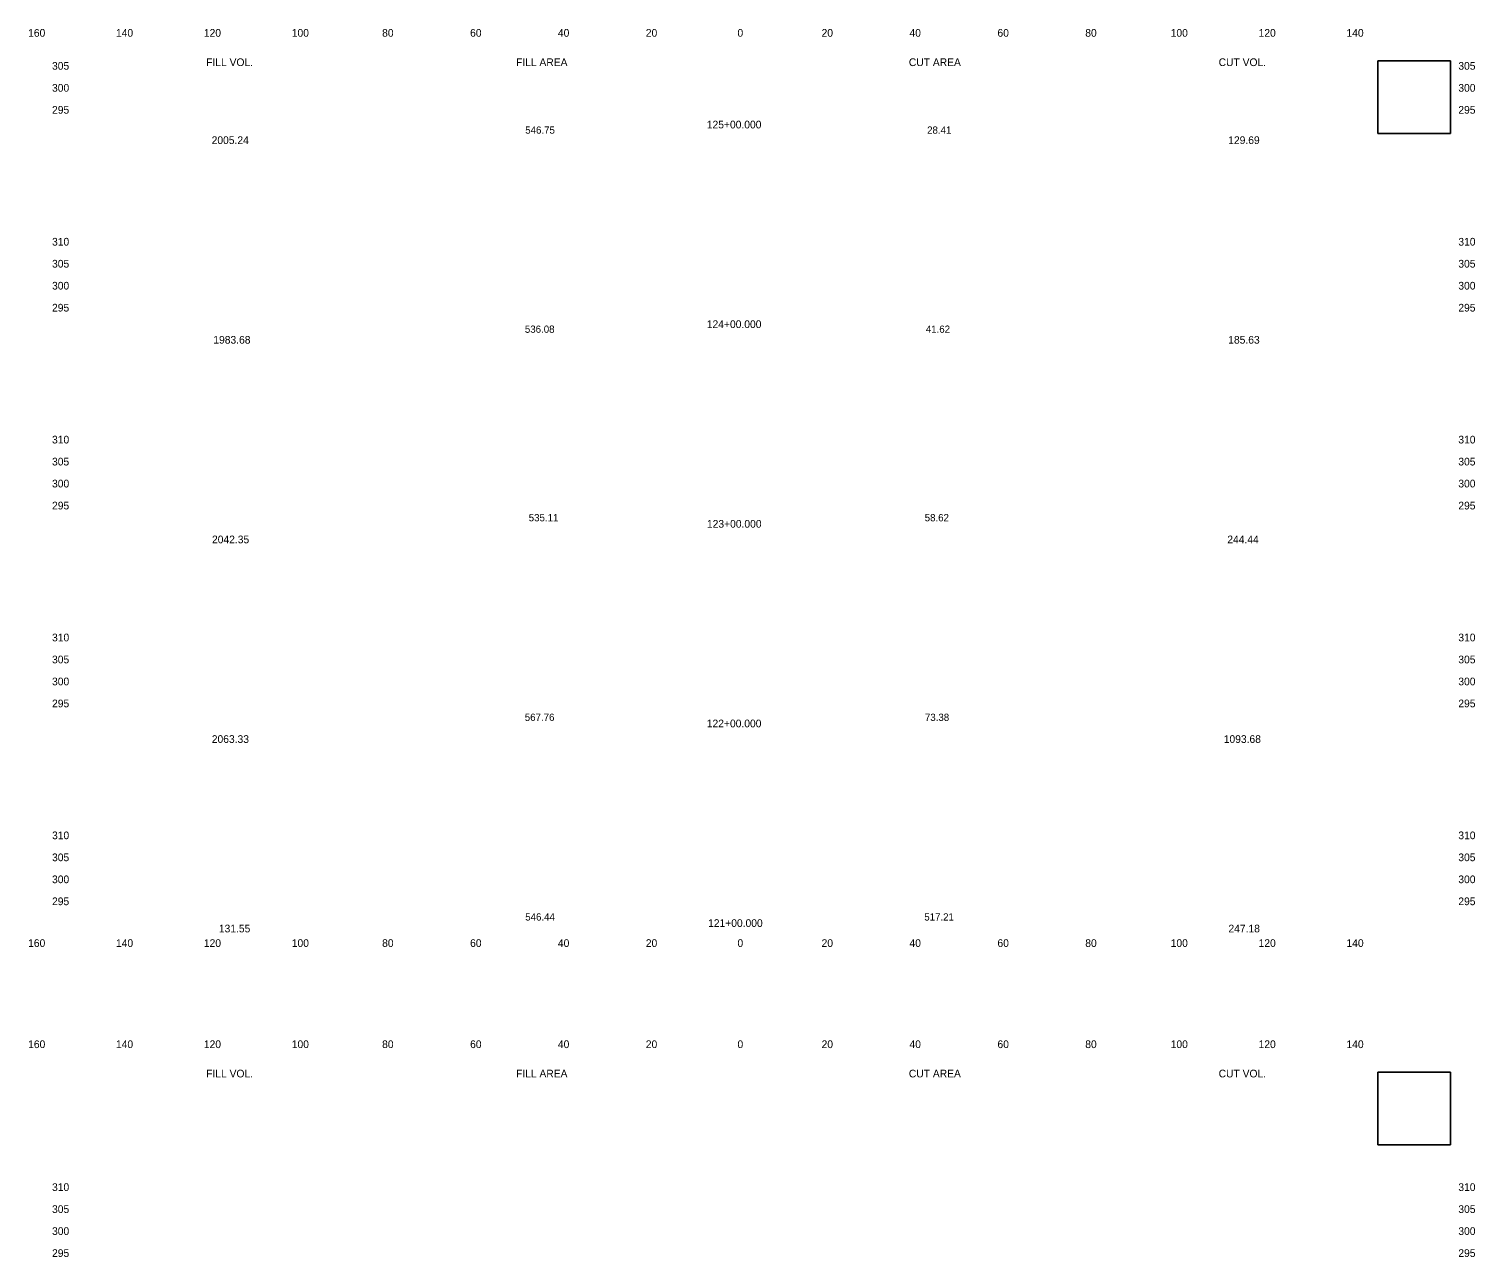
# Model space of a CAD drawing. Extents: x 21477 to 21806, y 6470 to 11049.
# Drawn here: x 21477.1 to 21806.1, y 8469.8 to 8749.1 of the extents above; entities that cross this region are included whole.
import ezdxf

# ---------------------------------------------------------------- set-up
doc = ezdxf.new("R2010")
doc.units = 0
for name, color, linetype in [('SHEET_CONSULTANT_STAMP', 7, 'Continuous'), ('XS_SHEET_EW_TX_AREA', 7, 'Continuous'), ('XS_SHEET_EW_TX_VOLUME', 7, 'Continuous'), ('XS_SHEET_LABELS_ELEVATION', 7, 'Continuous'), ('XS_SHEET_LABELS_OFFSET', 7, 'Continuous'), ('XS_SHEET_LABELS_STATION', 7, 'Continuous'), ('XS_SHEET_TX', 7, 'Continuous')]:
    doc.layers.add(name, color=color, linetype=linetype)

msp = doc.modelspace()

# ---------------------------------------------------------------- linework, layer by layer
at = {"layer": 'SHEET_CONSULTANT_STAMP'}
for points in [[(21784.04, 8725.34), (21800.54, 8725.34), (21800.54, 8741.84), (21784.04, 8741.84)], [(21784.04, 8495.34), (21800.54, 8495.34), (21800.54, 8511.84), (21784.04, 8511.84)]]:
    msp.add_lwpolyline(points, close=True, dxfattribs=at)

# ---------------------------------------------------------------- texts
at = {"layer": 'XS_SHEET_EW_TX_AREA'}
for s, p in [(' 546.75 ', (21589.4, 8725.29)), (' 28.41 ', (21680.85, 8725.29)), (' 536.08 ', (21589.32, 8680.01)), (' 41.62 ', (21680.55, 8680.01)), (' 535.11 ', (21590.2, 8637.14)), (' 58.62 ', (21680.3, 8637.14)), (' 567.76 ', (21589.3, 8591.74)), (' 73.38 ', (21680.35, 8591.74)), (' 546.44 ', (21589.4, 8546.34)), (' 517.21 ', (21680.2, 8546.34))]:
    msp.add_text(s, height=1.65, dxfattribs=at).set_placement(p)
at = {"layer": 'XS_SHEET_EW_TX_VOLUME'}
for s, p in [(' 2005.24 ', (21518.01, 8722.94)), (' 129.69 ', (21749.33, 8722.94)), (' 1983.68 ', (21518.39, 8677.54)), (' 185.63 ', (21749.33, 8677.54)), (' 2042.35 ', (21518.09, 8632.14)), (' 244.44 ', (21749.12, 8632.14)), (' 2063.33 ', (21518.04, 8586.74)), (' 1093.68 ', (21748.31, 8586.74)), (' 131.55 ', (21519.65, 8543.65)), (' 247.18 ', (21749.38, 8543.65))]:
    msp.add_text(s, height=1.75, dxfattribs=at).set_placement(p)
at = {"layer": 'XS_SHEET_LABELS_ELEVATION'}
for s, p in [('  305  ', (21481.04, 8739.84)), ('  305  ', (21801.04, 8739.84)), ('  300  ', (21481.04, 8734.84)), ('  300  ', (21801.04, 8734.84)), ('  295  ', (21481.04, 8729.84)), ('  295  ', (21801.04, 8729.84)), ('  310  ', (21481.04, 8699.84)), ('  310  ', (21801.04, 8699.84)), ('  305  ', (21481.04, 8694.84)), ('  305  ', (21801.04, 8694.84)), ('  300  ', (21481.04, 8689.84)), ('  300  ', (21801.04, 8689.84)), ('  295  ', (21481.04, 8684.84)), ('  295  ', (21801.04, 8684.84)), ('  310  ', (21481.04, 8654.84)), ('  310  ', (21801.04, 8654.84)), ('  305  ', (21481.04, 8649.84)), ('  305  ', (21801.04, 8649.84)), ('  300  ', (21481.04, 8644.84)), ('  300  ', (21801.04, 8644.84)), ('  295  ', (21481.04, 8639.84)), ('  295  ', (21801.04, 8639.84)), ('  310  ', (21481.04, 8609.84)), ('  310  ', (21801.04, 8609.84)), ('  305  ', (21481.04, 8604.84)), ('  305  ', (21801.04, 8604.84)), ('  300  ', (21481.04, 8599.84)), ('  300  ', (21801.04, 8599.84)), ('  295  ', (21481.04, 8594.84)), ('  295  ', (21801.04, 8594.84)), ('  310  ', (21481.04, 8564.84)), ('  310  ', (21801.04, 8564.84)), ('  305  ', (21481.04, 8559.84)), ('  305  ', (21801.04, 8559.84)), ('  300  ', (21481.04, 8554.84)), ('  300  ', (21801.04, 8554.84)), ('  295  ', (21481.04, 8549.84)), ('  295  ', (21801.04, 8549.84)), ('  310  ', (21481.04, 8484.84)), ('  310  ', (21801.04, 8484.84)), ('  305  ', (21481.04, 8479.84)), ('  305  ', (21801.04, 8479.84)), ('  300  ', (21481.04, 8474.84)), ('  300  ', (21801.04, 8474.84)), ('  295  ', (21481.04, 8469.84)), ('  295  ', (21801.04, 8469.84))]:
    msp.add_text(s, height=1.75, dxfattribs=at).set_placement(p)
at = {"layer": 'XS_SHEET_LABELS_OFFSET'}
for s, p in [('  160  ', (21475.6, 8747.34)), ('  140  ', (21495.59, 8747.34)), ('  120  ', (21515.59, 8747.34)), ('  100  ', (21535.59, 8747.34)), ('  80  ', (21556.15, 8747.34)), ('  60  ', (21576.17, 8747.34)), ('  40  ', (21596.15, 8747.34)), ('  20  ', (21616.15, 8747.34)), ('  0  ', (21637.01, 8747.34)), ('  0  ', (21637.01, 8747.34)), ('  20  ', (21656.15, 8747.34)), ('  40  ', (21676.15, 8747.34)), ('  60  ', (21696.17, 8747.34)), ('  80  ', (21716.15, 8747.34)), ('  100  ', (21735.59, 8747.34)), ('  120  ', (21755.59, 8747.34)), ('  140  ', (21775.59, 8747.34)), ('  160  ', (21475.6, 8540.34)), ('  140  ', (21495.59, 8540.34)), ('  120  ', (21515.59, 8540.34)), ('  100  ', (21535.59, 8540.34)), ('  80  ', (21556.15, 8540.34)), ('  60  ', (21576.17, 8540.34)), ('  40  ', (21596.15, 8540.34)), ('  20  ', (21616.15, 8540.34)), ('  0  ', (21637.01, 8540.34)), ('  0  ', (21637.01, 8540.34)), ('  20  ', (21656.15, 8540.34)), ('  40  ', (21676.15, 8540.34)), ('  60  ', (21696.17, 8540.34)), ('  80  ', (21716.15, 8540.34)), ('  100  ', (21735.59, 8540.34)), ('  120  ', (21755.59, 8540.34)), ('  140  ', (21775.59, 8540.34)), ('  160  ', (21475.6, 8517.34)), ('  140  ', (21495.59, 8517.34)), ('  120  ', (21515.59, 8517.34)), ('  100  ', (21535.59, 8517.34)), ('  80  ', (21556.15, 8517.34)), ('  60  ', (21576.17, 8517.34)), ('  40  ', (21596.15, 8517.34)), ('  20  ', (21616.15, 8517.34)), ('  0  ', (21637.01, 8517.34)), ('  0  ', (21637.01, 8517.34)), ('  20  ', (21656.15, 8517.34)), ('  40  ', (21676.15, 8517.34)), ('  60  ', (21696.17, 8517.34)), ('  80  ', (21716.15, 8517.34)), ('  100  ', (21735.59, 8517.34)), ('  120  ', (21755.59, 8517.34)), ('  140  ', (21775.59, 8517.34))]:
    msp.add_text(s, height=1.75, dxfattribs=at).set_placement(p)
at = {"layer": 'XS_SHEET_LABELS_STATION'}
for s, p in [('  125+00.000  ', (21630.03, 8726.49)), ('  124+00.000  ', (21630.03, 8681.09)), ('  123+00.000  ', (21630.06, 8635.69)), ('  122+00.000  ', (21630.03, 8590.29)), ('  121+00.000  ', (21630.32, 8544.89))]:
    msp.add_text(s, height=1.75, dxfattribs=at).set_placement(p)
at = {"layer": 'XS_SHEET_TX'}
for s, p in [('FILL VOL.', (21517.41, 8740.67)), ('FILL AREA', (21587.92, 8740.67)), ('CUT AREA', (21677.31, 8740.67)), ('CUT VOL.', (21747.8, 8740.67)), ('FILL VOL.', (21517.41, 8510.67)), ('FILL AREA', (21587.92, 8510.67)), ('CUT AREA', (21677.31, 8510.67)), ('CUT VOL.', (21747.8, 8510.67))]:
    msp.add_text(s, height=1.75, dxfattribs=at).set_placement(p)

doc.saveas('drawing.dxf')
